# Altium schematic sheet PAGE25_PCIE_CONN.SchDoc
size 381 x 381 mm; SheetNumber: 26; SheetTotal: 28
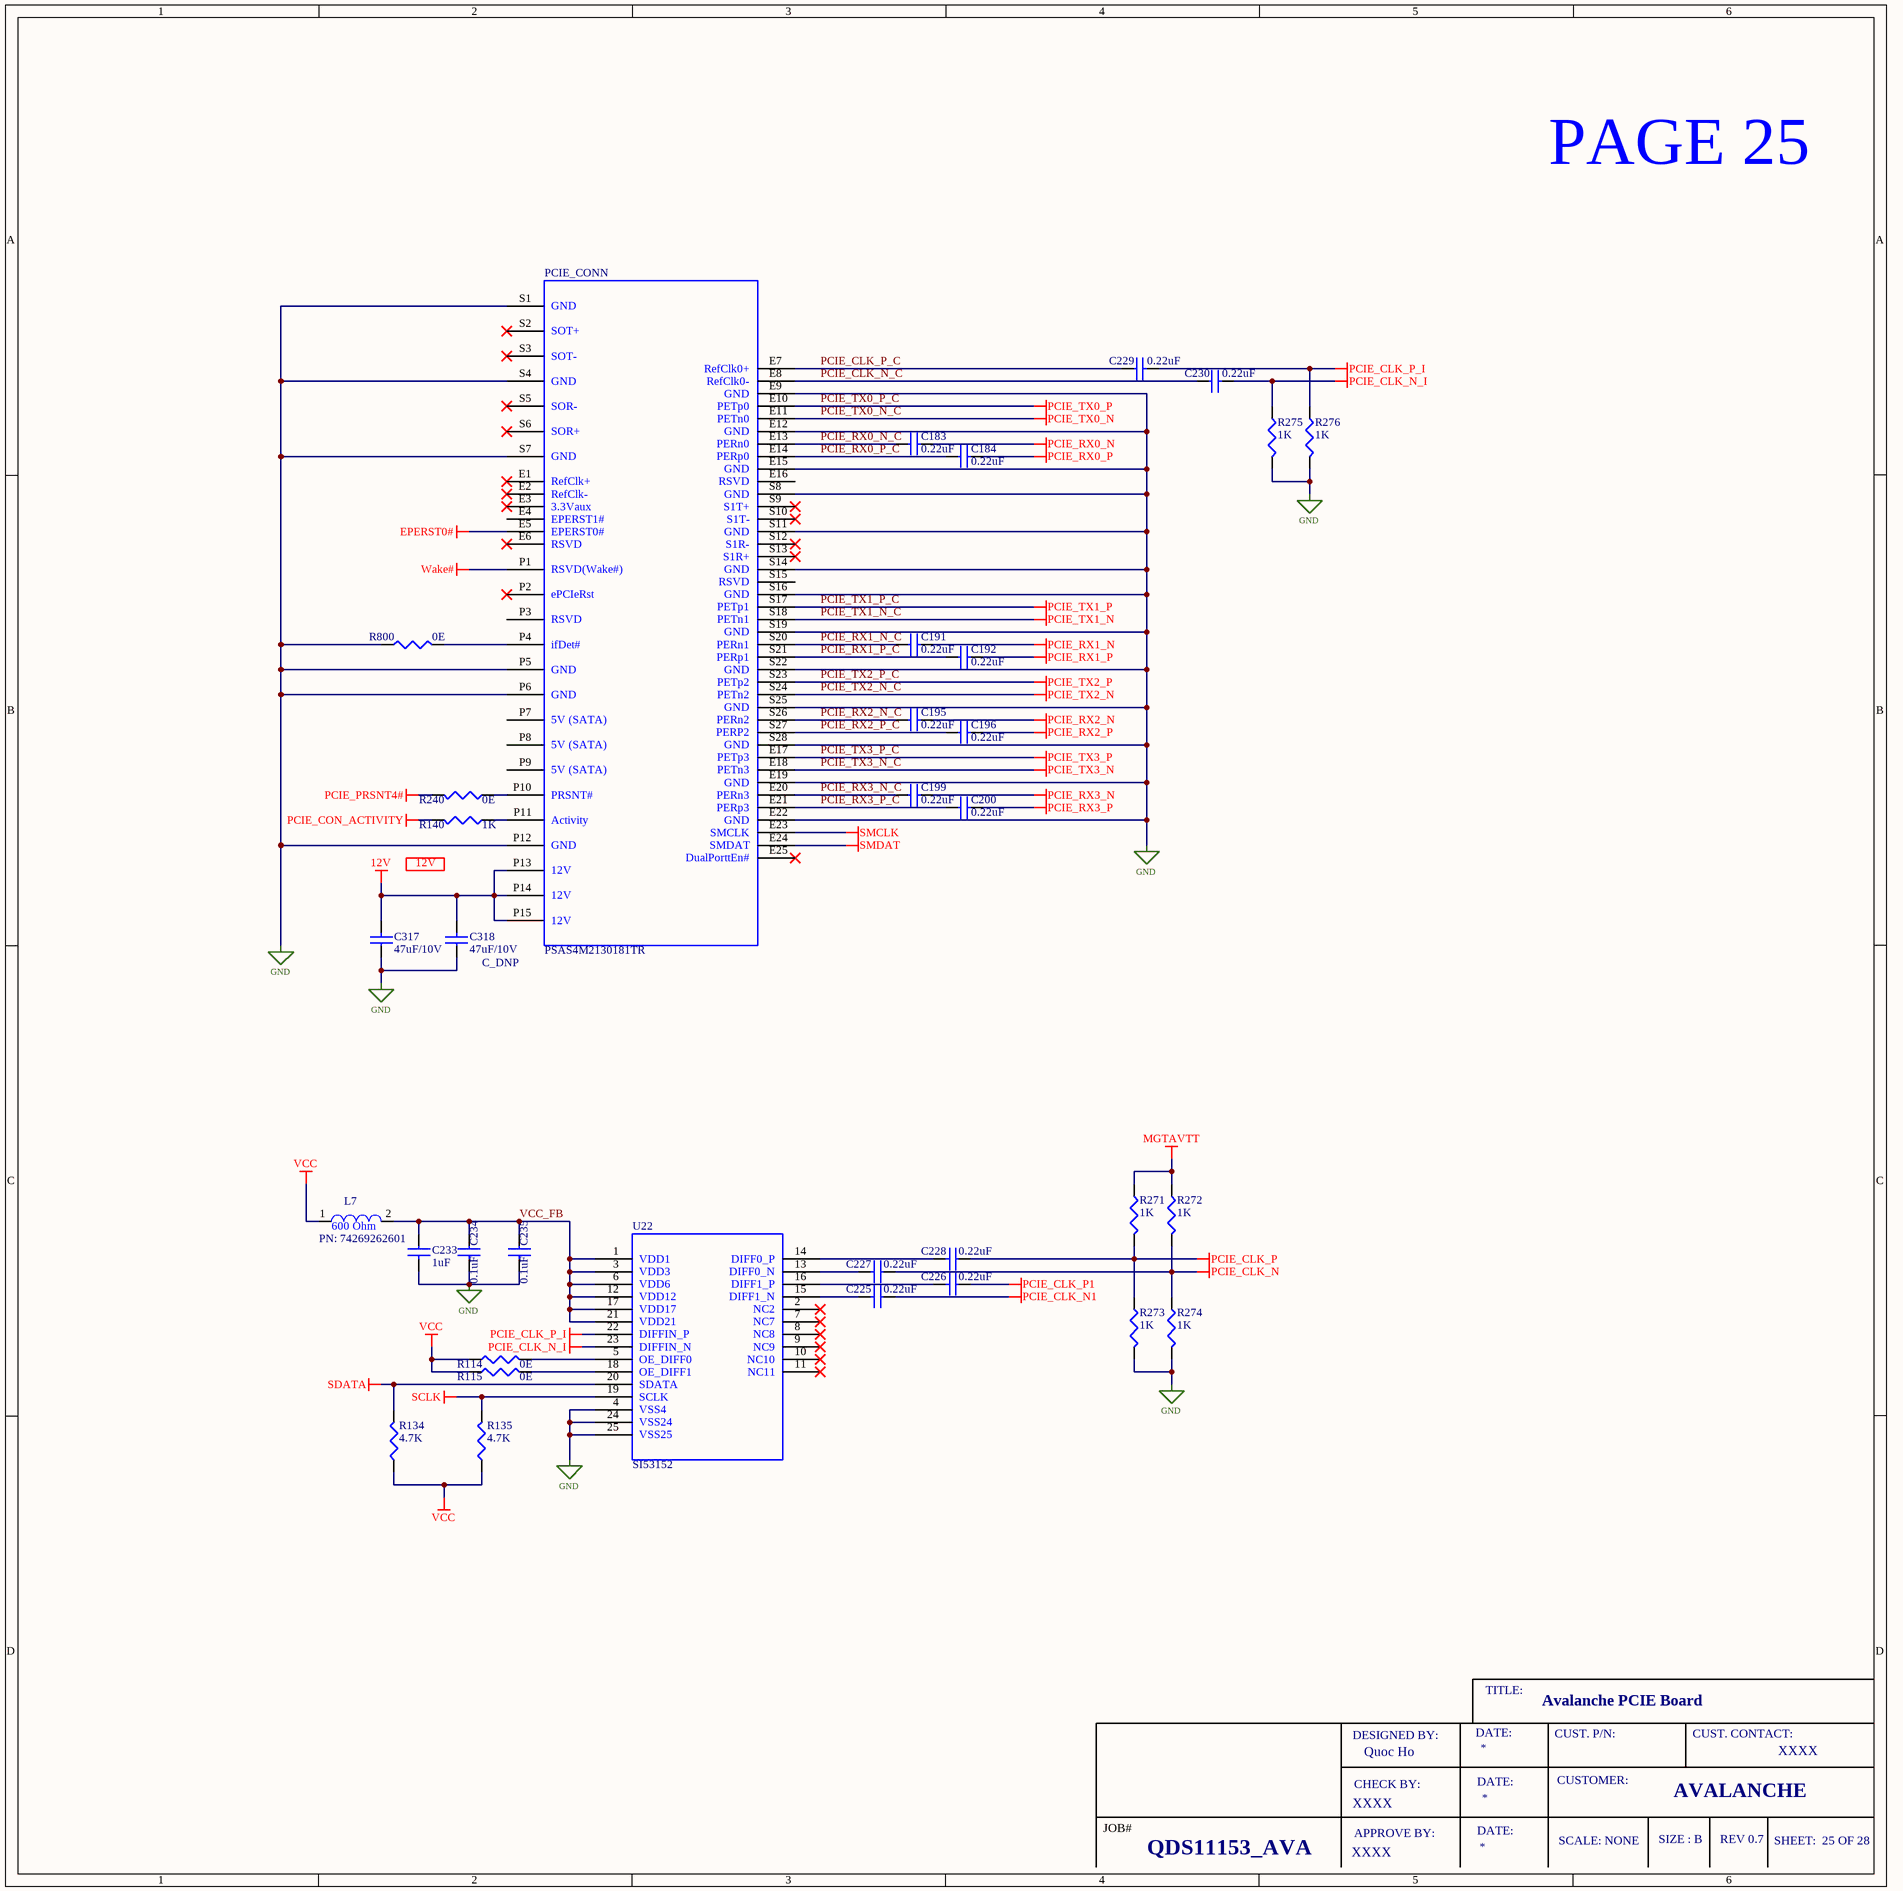
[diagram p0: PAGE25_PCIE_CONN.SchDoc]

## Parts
C183  0.22uF  [CN_0201]
C184  0.22uF  [CN_0201]
C191  0.22uF  [CN_0201]
C192  0.22uF  [CN_0201]
C195  0.22uF  [CN_0201]
C196  0.22uF  [CN_0201]
C199  0.22uF  [CN_0201]
C200  0.22uF  [CN_0201]
C225  0.22uF  [CN_0402]
C226  0.22uF  [CN_0402]
C227  0.22uF  [CN_0402]
C228  0.22uF  [CN_0402]
C229  0.22uF  [CN_0201]
C230  0.22uF  [CN_0201]
C233  1uF  [CN_0402]
C234  0.1uF  [CN_0402]
C235  0.1uF  [CN_0402]
C317  47uF/10V  [CN_1210]
C318  47uF/10V  [CN_1210]
L7  PN: 74269262601  [74269262601]
PCIE_CONN  PSAS4M2130181TR  [AMPHENOL_PSAS4M2130021TR]
R114  0E  [RN_0402]
R115  0E  [RN_0402]
R134  4.7K  [RN_0402]
R135  4.7K  [RN_0402]
R140  1K  [RN_0402]
R240  0E  [RN_0402]
R271  1K  [RN_0402]
R272  1K  [RN_0402]
R273  1K  [RN_0402]
R274  1K  [RN_0402]
R275  1K  [RN_0201]
R276  1K  [RN_0201]
R800  0E  [RN_0402]
U22  SI53152  [SI53152 - QFN24]

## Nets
12V: C317.2 C318.2 PCIE_CONN.P13(12V) PCIE_CONN.P14(12V) PCIE_CONN.P15(12V)
EPERST0#: PCIE_CONN.E5(EPERST0#)
GND: C233.2 C234.2 C235.2 C317.1 C318.1 PCIE_CONN.E9(GND) PCIE_CONN.E12(GND) PCIE_CONN.E15(GND) PCIE_CONN.E19(GND) PCIE_CONN.E22(GND) PCIE_CONN.P5(GND) PCIE_CONN.P6(GND) PCIE_CONN.P12(GND) PCIE_CONN.S1(GND) PCIE_CONN.S4(GND) PCIE_CONN.S7(GND) PCIE_CONN.S8(GND) PCIE_CONN.S11(GND) PCIE_CONN.S14(GND) PCIE_CONN.S16(GND) PCIE_CONN.S19(GND) PCIE_CONN.S22(GND) PCIE_CONN.S25(GND) PCIE_CONN.S28(GND) R273.2 R274.2 R275.2 R276.2 R800.1 U22.4(VSS4) U22.24(VSS24) U22.25(VSS25)
MGTAVTT: R271.1 R272.1
PCIE_CLK_N: C227.1 R272.2 R274.1
PCIE_CLK_N1: C225.1
PCIE_CLK_N_I: C230.2 R275.1 U22.23(DIFFIN_N)
PCIE_CLK_P: C228.1 R271.2 R273.1
PCIE_CLK_P1: C226.1
PCIE_CLK_P_I: C229.2 R276.1 U22.22(DIFFIN_P)
PCIE_CON_ACTIVITY: R140.2
PCIE_PRSNT4#: R240.2
PCIE_RX0_N: C183.2
PCIE_RX0_P: C184.2
PCIE_RX1_N: C191.2
PCIE_RX1_P: C192.2
PCIE_RX2_N: C195.2
PCIE_RX2_P: C196.2
PCIE_RX3_N: C199.2
PCIE_RX3_P: C200.2
PCIE_TX0_N_C: PCIE_CONN.E11(PETn0)  [also labelled PCIE_TX0_N]
PCIE_TX0_P_C: PCIE_CONN.E10(PETp0)  [also labelled PCIE_TX0_P]
PCIE_TX1_N_C: PCIE_CONN.S18(PETn1)  [also labelled PCIE_TX1_N]
PCIE_TX1_P_C: PCIE_CONN.S17(PETp1)  [also labelled PCIE_TX1_P]
PCIE_TX2_N_C: PCIE_CONN.S24(PETn2)  [also labelled PCIE_TX2_N]
PCIE_TX2_P_C: PCIE_CONN.S23(PETp2)  [also labelled PCIE_TX2_P]
PCIE_TX3_N_C: PCIE_CONN.E18(PETn3)  [also labelled PCIE_TX3_N]
PCIE_TX3_P_C: PCIE_CONN.E17(PETp3)  [also labelled PCIE_TX3_P]
SCLK: R135.2 U22.19(SCLK)
SDATA: R134.2 U22.20(SDATA)
SMCLK: PCIE_CONN.E23(SMCLK)
SMDAT: PCIE_CONN.E24(SMDAT)
VCC: L7.1 R114.1 R115.1 R134.1 R135.1
Wake#: PCIE_CONN.P1(RSVD(Wake#))
PCIE_CLK_N_C: C230.1 PCIE_CONN.E8(RefClk0-)
PCIE_CLK_P_C: C229.1 PCIE_CONN.E7(RefClk0+)
PCIE_RX0_N_C: C183.1 PCIE_CONN.E13(PERn0)
PCIE_RX0_P_C: C184.1 PCIE_CONN.E14(PERp0)
PCIE_RX1_N_C: C191.1 PCIE_CONN.S20(PERn1)
PCIE_RX1_P_C: C192.1 PCIE_CONN.S21(PERp1)
PCIE_RX2_N_C: C195.1 PCIE_CONN.S26(PERn2)
PCIE_RX2_P_C: C196.1 PCIE_CONN.S27(PERP2)
PCIE_RX3_N_C: C199.1 PCIE_CONN.E20(PERn3)
PCIE_RX3_P_C: C200.1 PCIE_CONN.E21(PERp3)
VCC_FB: C233.1 C234.1 C235.1 L7.2 U22.1(VDD1) U22.3(VDD3) U22.6(VDD6) U22.12(VDD12) U22.17(VDD17) U22.21(VDD21)
NetC225_2: C225.2 U22.15(DIFF1_N)
NetC226_2: C226.2 U22.16(DIFF1_P)
NetC227_2: C227.2 U22.13(DIFF0_N)
NetC228_2: C228.2 U22.14(DIFF0_P)
NetPCIE_CONN_P4: PCIE_CONN.P4(ifDet#) R800.2
NetPCIE_CONN_P10: PCIE_CONN.P10(PRSNT#) R240.1
NetPCIE_CONN_P11: PCIE_CONN.P11(Activity) R140.1
NetR114_2: R114.2 U22.5(OE_DIFF0)
NetR115_2: R115.2 U22.18(OE_DIFF1)

Not connected (* = marked no-connect by the designer): PCIE_CONN E1(RefClk+)* E2(RefClk-)* E3(3.3Vaux)* E4(EPERST1#) E6(RSVD)* E16(RSVD) E25(DualPorttEn#)* P2(ePCIeRst)* P3(RSVD) P7(5V_(SATA)) P8(5V_(SATA)) P9(5V_(SATA)) S2(SOT+)* S3(SOT-)* S5(SOR-)* S6(SOR+)* S9(S1T+)* S10(S1T-)* S12(S1R-)* S13(S1R+)* S15(RSVD); U22 2(NC2)* 7(NC7)* 8(NC8)* 9(NC9)* 10(NC10)* 11(NC11)*

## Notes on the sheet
- PAGE 25
- (near R140) 12V
- (near C318) C_DNP
- (near L7) 600 Ohm
- TITLE:
- Avalanche PCIE Board
- DESIGNED BY:
- CHECK BY:
- Quoc Ho
- DATE:
- CUST. P/N:
- CUSTOMER:
- CUST. CONTACT:
- XXXX
- JOB#
- APPROVE BY:
- SCALE: NONE
- SIZE : B
- AVALANCHE
- REV 0.7
- SHEET:  25 OF 28
- QDS11153_AVA

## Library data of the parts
C183 C184 C191 C192 C195 C196 C199 C200 C229 C230 = CAP: CAP CER 0.22UF 25V X5R 0201; Manufacturer Part Number: GRM033R61E224KE01D; Manufacturer: Murata Electronics
C225-C228 = CAP: CAP CER 0.22UF 50V X5R 0402; Manufacturer Part Number: GRM155R61H224KE01W; Manufacturer: Murata Electronics
C233 = CAP: CAP CER 1UF 25V X5R 0402; Manufacturer: TDK CORPORATION; Manufacturer Part Number: C1005X5R1E105K050BC
C234 C235 = CAP: CAP CER 0.1UF 50V X7R 0402; Manufacturer Part Number: GCM155R71H104KE02J; Manufacturer: Murata Electronics
C317 C318 = CAP: CAP CER 47UF 10V X6S 1210; Manufacturer Part Number: GRT32EC81A476KE13L; Manufacturer: Murata Electronics
L7 = INDUCTOR: WE-TMSB SMT EMI SUPPRESSION FERR; Manufacturer: Würth Elektronik
PCIE_CONN = PCIE_CON: SAS/PCIE 4.0 (U.2 & U.3) CONNECT; Manufacturer: Amphenol ICC (FCI)
R114 R115 R800 = RES: RES 0 OHM JUMPER 1/16W 0402; Manufacturer Part Number: RC0402FR-070RL; Manufacturer: YAGEO
R134 R135 = RES: RES 4.7K OHM 1% 1/16W 0402; Manufacturer Part Number: RC0402FR-134K7L; Manufacturer: YAGEO
R140 R271-R274 = RES: RES 1K OHM 1% 1/16W 0402; Manufacturer Part Number: RC0402FR-131KL; Manufacturer: YAGEO
R240 = RES: RES 0 OHM JUMPER 1/16W 0402; Manufacturer: YAGEO; Manufacturer Part Number: RC0402FR-070RL_DNI
R275 R276 = RES: RES 1K OHM 1% 1/20W 0201; Manufacturer Part Number: RC0201FR-131KL; Manufacturer: YAGEO
U22 = SI53152: IC PCIE BUFFER 100MHZ 1IN 2OUT; Manufacturer Part Number: SI53152-A01AGM; Manufacturer: Skyworks Solutions Inc.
